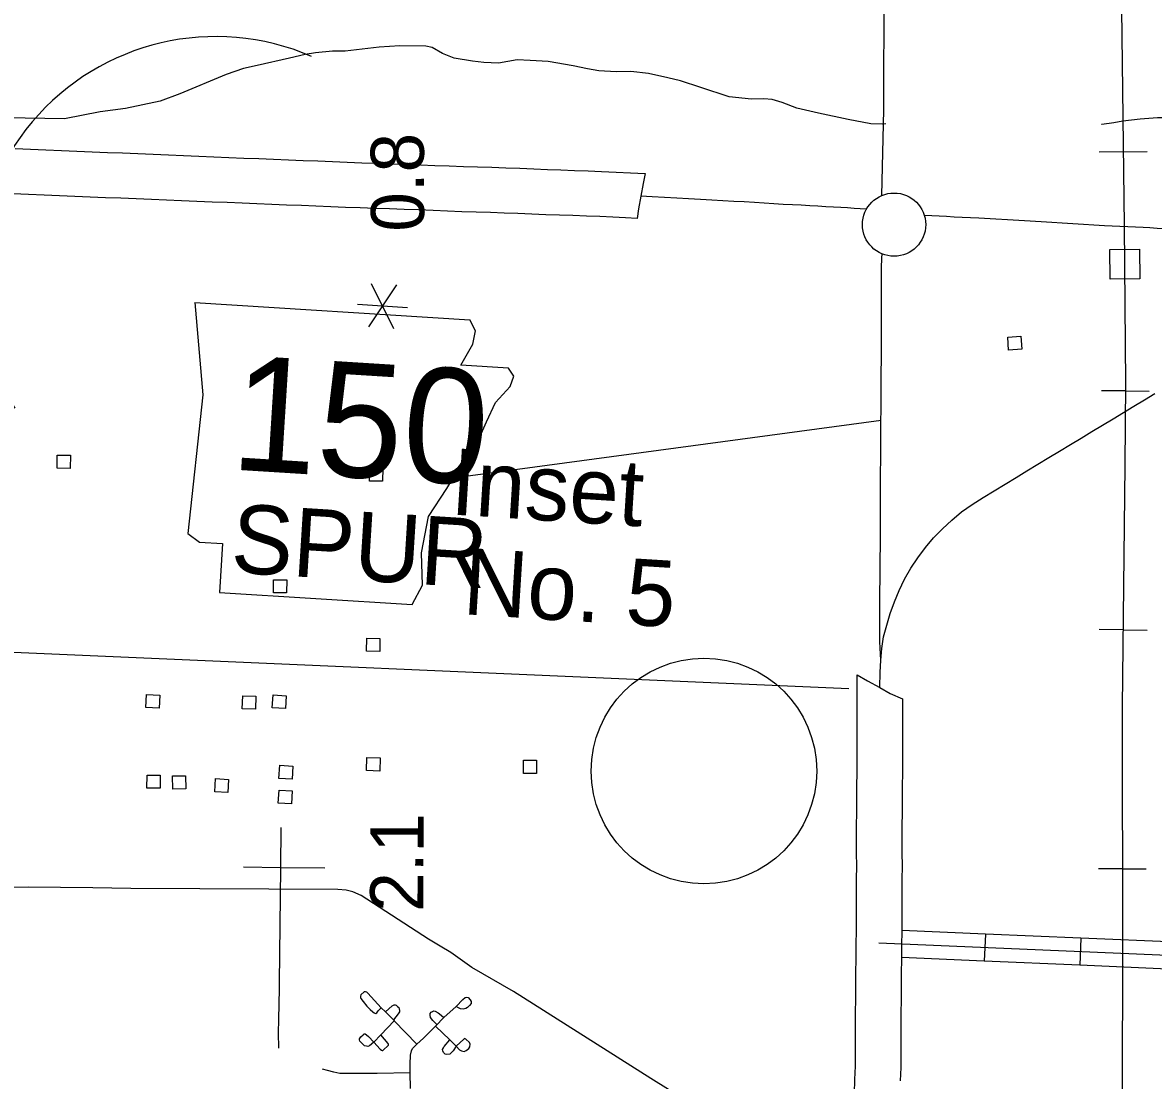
# Model space of a CAD drawing. Extents: x 1366406 to 1373462, y 376856 to 381998.
# Drawn here: x 1369108.1 to 1369209.2, y 380173.9 to 380268.5 of the extents above; entities that cross this region are included whole.
import ezdxf

# ---------------------------------------------------------------- set-up
doc = ezdxf.new("R2010")
doc.units = 0
for name, color, linetype in [('10', 7, 'Continuous'), ('15', 7, 'Continuous'), ('21', 7, 'Continuous'), ('24', 7, 'Continuous'), ('31', 7, 'Continuous'), ('32', 7, 'Continuous'), ('33', 7, 'Continuous'), ('35', 7, 'Continuous'), ('40', 7, 'Continuous'), ('43', 7, 'Continuous'), ('48', 7, 'Continuous'), ('5', 7, 'Continuous'), ('56', 7, 'Continuous'), ('63', 7, 'Continuous')]:
    doc.layers.add(name, color=color, linetype=linetype)

msp = doc.modelspace()

# ---------------------------------------------------------------- linework, layer by layer
at = {"layer": '10'}
for points in [[(1369107.42, 380257.24), (1369108.79, 380257.18), (1369110.16, 380257.12), (1369111.54, 380257.07), (1369112.92, 380257.01), (1369114.29, 380256.95), (1369115.66, 380256.89), (1369117.02, 380256.84), (1369118.38, 380256.79), (1369119.75, 380256.73), (1369121.12, 380256.68), (1369122.48, 380256.62), (1369123.84, 380256.56), (1369125.19, 380256.5), (1369126.53, 380256.44), (1369127.87, 380256.39), (1369129.2, 380256.34), (1369130.53, 380256.28), (1369131.85, 380256.23), (1369133.17, 380256.18), (1369134.49, 380256.13), (1369135.8, 380256.07), (1369137.11, 380256.02), (1369138.42, 380255.97), (1369139.73, 380255.93), (1369141.03, 380255.88), (1369142.35, 380255.84), (1369143.66, 380255.79), (1369144.95, 380255.73), (1369146.23, 380255.69), (1369147.51, 380255.64), (1369148.78, 380255.6), (1369150.05, 380255.57), (1369151.31, 380255.52), (1369152.57, 380255.47), (1369153.8, 380255.42), (1369155.02, 380255.37), (1369156.24, 380255.32), (1369157.45, 380255.28), (1369158.67, 380255.24), (1369159.87, 380255.19), (1369163.78, 380255.02), (1369163.59, 380254.12), (1369163.37, 380252.99), (1369163.16, 380251.85), (1369163.05, 380250.98)], [(1369163.05, 380250.98), (1369162.02, 380251.04), (1369160.87, 380251.09), (1369159.7, 380251.15), (1369158.51, 380251.19), (1369157.31, 380251.24), (1369156.1, 380251.28), (1369154.87, 380251.32), (1369153.64, 380251.37), (1369152.39, 380251.42), (1369151.16, 380251.47), (1369149.92, 380251.52), (1369148.66, 380251.55), (1369147.38, 380251.59), (1369146.09, 380251.64), (1369144.79, 380251.69), (1369143.49, 380251.74), (1369142.2, 380251.79), (1369140.9, 380251.83), (1369139.59, 380251.88), (1369138.27, 380251.92), (1369136.96, 380251.97), (1369135.64, 380252.03), (1369134.32, 380252.08), (1369133.01, 380252.13), (1369131.69, 380252.18), (1369130.36, 380252.24), (1369129.04, 380252.29), (1369127.71, 380252.34), (1369126.37, 380252.4), (1369125.02, 380252.45), (1369123.66, 380252.51), (1369122.3, 380252.57), (1369120.94, 380252.63), (1369119.59, 380252.69), (1369118.23, 380252.74), (1369116.86, 380252.79), (1369115.49, 380252.84), (1369114.11, 380252.9), (1369112.74, 380252.96), (1369111.37, 380253.02), (1369110, 380253.08), (1369108.61, 380253.13), (1369107.22, 380253.2)], [(1369183.57, 380251.82), (1369183.01, 380251.85), (1369182.46, 380251.88), (1369181.88, 380251.92), (1369181.27, 380251.95), (1369180.62, 380251.99), (1369179.94, 380252.03), (1369179.23, 380252.08), (1369178.5, 380252.12), (1369177.73, 380252.16), (1369176.94, 380252.2), (1369176.13, 380252.24), (1369175.29, 380252.29), (1369174.42, 380252.35), (1369173.54, 380252.41), (1369172.63, 380252.46), (1369171.69, 380252.51), (1369170.73, 380252.56), (1369169.73, 380252.63), (1369168.71, 380252.69), (1369167.66, 380252.75), (1369166.6, 380252.81), (1369165.51, 380252.86), (1369164.4, 380252.93), (1369163.37, 380252.99)], [(1369188.75, 380251.27), (1369189.43, 380251.25), (1369190.07, 380251.22), (1369190.74, 380251.18), (1369191.42, 380251.14), (1369192.13, 380251.11), (1369192.87, 380251.07), (1369193.63, 380251.03), (1369197.7, 380250.8), (1369199.21, 380250.7), (1369204.87, 380250.36)], [(1369204.87, 380250.36), (1369208.32, 380250.19), (1369208.92, 380250.16), (1369209.59, 380250.12), (1369210.32, 380250.08), (1369211.11, 380250.03), (1369211.95, 380249.97), (1369212.84, 380249.92), (1369213.76, 380249.87), (1369214.71, 380249.82), (1369215.69, 380249.76), (1369216.69, 380249.7), (1369217.71, 380249.63), (1369218.74, 380249.57), (1369219.74, 380249.5), (1369220.72, 380249.44), (1369221.66, 380249.38), (1369222.55, 380249.33), (1369223.36, 380249.28), (1369224.08, 380249.24), (1369224.69, 380249.23)], [(1369184.85, 380211.44), (1369184.82, 380212.04), (1369184.8, 380212.54), (1369184.78, 380213.12), (1369184.78, 380213.76), (1369184.78, 380214.45), (1369184.78, 380215.19), (1369184.77, 380215.98), (1369184.77, 380216.81), (1369184.78, 380217.7), (1369184.79, 380218.62), (1369184.79, 380219.59), (1369184.8, 380220.6), (1369184.81, 380221.63), (1369184.81, 380222.69), (1369184.81, 380223.77), (1369184.81, 380224.88), (1369184.81, 380225.99), (1369184.82, 380227.12), (1369184.83, 380228.26), (1369184.84, 380229.39), (1369184.85, 380230.53), (1369184.85, 380231.66), (1369184.86, 380232.79), (1369184.87, 380233.91), (1369184.88, 380235.03), (1369184.89, 380236.13), (1369184.89, 380237.23), (1369184.9, 380238.33), (1369184.91, 380239.42), (1369184.91, 380240.5), (1369184.91, 380241.58), (1369184.91, 380242.63), (1369184.91, 380243.66), (1369184.91, 380244.66), (1369184.9, 380245.63), (1369184.91, 380246.57), (1369184.93, 380247.42), (1369184.96, 380247.81)]]:
    msp.add_lwpolyline(points, dxfattribs=at)
at = {"layer": '15'}
for points in [[(1369184.85, 380211.44), (1369184.94, 380212.5), (1369185.09, 380213.55), (1369185.4, 380214.6), (1369185.7, 380215.64), (1369186.07, 380216.68), (1369186.49, 380217.7), (1369186.98, 380218.71), (1369187.54, 380219.68), (1369188.16, 380220.62), (1369188.84, 380221.53), (1369189.57, 380222.4), (1369190.36, 380223.22), (1369191.2, 380224), (1369192.08, 380224.73), (1369193.02, 380225.4), (1369194, 380226.01), (1369194.99, 380226.6), (1369195.98, 380227.2), (1369196.96, 380227.8), (1369197.93, 380228.4), (1369198.9, 380228.99), (1369199.87, 380229.58), (1369200.85, 380230.16), (1369201.83, 380230.75), (1369202.79, 380231.33), (1369203.74, 380231.91), (1369204.68, 380232.5), (1369205.63, 380233.06), (1369206.57, 380233.63), (1369207.5, 380234.19), (1369208.44, 380234.76), (1369209.37, 380235.32)], [(1369184.76, 380209), (1369184.79, 380210.38), (1369184.85, 380211.44)], [(1369182.51, 380172.69), (1369182.53, 380173.93), (1369182.58, 380175.12), (1369182.59, 380176.29), (1369182.6, 380177.48), (1369182.6, 380178.69), (1369182.6, 380179.92), (1369182.62, 380181.11), (1369182.63, 380182.3), (1369182.63, 380183.5), (1369182.64, 380184.7), (1369182.65, 380186.16), (1369182.67, 380187.11), (1369182.68, 380188.29), (1369182.69, 380189.47), (1369182.69, 380190.67), (1369182.69, 380191.86), (1369182.7, 380193.04), (1369182.69, 380194.23), (1369182.69, 380195.44), (1369182.69, 380196.64), (1369182.7, 380197.84), (1369182.71, 380199.03), (1369182.72, 380200.21), (1369182.73, 380201.39), (1369182.73, 380202.55), (1369182.73, 380203.71), (1369182.75, 380210.14), (1369183.65, 380209.6), (1369184.76, 380209), (1369185.7, 380208.48), (1369186.79, 380208)], [(1369186.79, 380208), (1369186.78, 380203.71), (1369186.78, 380202.55), (1369186.78, 380201.37), (1369186.77, 380200.18), (1369186.76, 380198.99), (1369186.75, 380197.81), (1369186.74, 380196.62), (1369186.74, 380195.44), (1369186.74, 380194.25), (1369186.75, 380193.04), (1369186.74, 380191.84), (1369186.74, 380190.65), (1369186.74, 380189.46), (1369186.73, 380188.26), (1369186.72, 380187.05), (1369186.7, 380186.11), (1369186.69, 380184.68), (1369186.68, 380183.48), (1369186.68, 380182.28), (1369186.67, 380181.07), (1369186.65, 380179.88), (1369186.65, 380178.69), (1369186.65, 380177.47), (1369186.64, 380176.25), (1369186.63, 380175.01), (1369186.58, 380173.82)]]:
    msp.add_lwpolyline(points, dxfattribs=at)
at = {"layer": '21'}
for p, q in [((1369123.47, 380243.47), (1369124.19, 380235.19)), ((1369148.58, 380240.94), (1369148.07, 380241.92)), ((1369148.36, 380239.72), (1369148.58, 380240.94)), ((1369147.29, 380237.86), (1369148.36, 380239.72)), ((1369151.53, 380237.6), (1369147.29, 380237.86)), ((1369152.03, 380236.88), (1369151.53, 380237.6)), ((1369151.7, 380235.94), (1369152.03, 380236.88)), ((1369124.19, 380235.19), (1369122.86, 380222.78)), ((1369150.37, 380234.51), (1369151.7, 380235.94)), ((1369149.58, 380232.78), (1369150.37, 380234.51)), ((1369148.62, 380230.64), (1369149.58, 380232.78)), ((1369147.12, 380228.67), (1369148.62, 380230.64)), ((1369146.04, 380226.82), (1369147.12, 380228.67)), ((1369144.38, 380224.31), (1369146.04, 380226.82)), ((1369143.76, 380221.06), (1369144.38, 380224.31)), ((1369122.86, 380222.78), (1369123.91, 380222.03)), ((1369123.91, 380222.03), (1369125.96, 380221.9)), ((1369125.96, 380221.9), (1369125.69, 380217.52)), ((1369143.85, 380218.17), (1369143.76, 380221.06)), ((1369142.92, 380216.44), (1369143.85, 380218.17)), ((1369125.69, 380217.52), (1369142.92, 380216.44))]:
    msp.add_line(p, q, dxfattribs=at)
for points in [[(1369123.47, 380243.47), (1369148.07, 380241.92)], [(1369146.6, 380227.77), (1369184.87, 380232.92)]]:
    msp.add_lwpolyline(points, dxfattribs=at)
at = {"layer": '24'}
msp.add_circle((1369186.04, 380250.43), 2.83, dxfattribs=at)
at = {"layer": '31'}
msp.add_lwpolyline([(1369184.93, 380253.04), (1369185.11, 380260.71)], dxfattribs=at)
at = {"layer": '32'}
for p, q in [((1369194.21, 380186.95), (1369194.1, 380184.52)), ((1369202.75, 380186.59), (1369202.65, 380184.16))]:
    msp.add_line(p, q, dxfattribs=at)
for points in [[(1369185.11, 380260.71), (1369185.19, 380282.45)], [(1369194.21, 380186.95), (1369186.72, 380187.27)], [(1369202.75, 380186.59), (1369194.21, 380186.95)], [(1369211.3, 380186.22), (1369202.75, 380186.59)], [(1369228.34, 380184.35), (1369227.29, 380184.33), (1369184.68, 380186.14)], [(1369194.1, 380184.52), (1369186.69, 380184.84)], [(1369202.65, 380184.16), (1369194.1, 380184.52)], [(1369211.2, 380183.79), (1369202.65, 380184.16)]]:
    msp.add_lwpolyline(points, dxfattribs=at)
at = {"layer": '33'}
for points in [[(1369131.18, 380196.5), (1369131.14, 380192.89), (1369131.03, 380182.58), (1369131.04, 380182.35), (1369131.04, 380182.07), (1369130.96, 380179.3), (1369130.95, 380178.11), (1369130.96, 380176.73)], [(1369135.11, 380192.86), (1369131.16, 380192.87), (1369127.85, 380192.95)], [(1369140.16, 380180.34), (1369138.96, 380181.67), (1369138.86, 380181.75), (1369138.75, 380181.79), (1369138.63, 380181.78), (1369138.34, 380181.51), (1369138.29, 380181.38), (1369138.3, 380181.27), (1369138.34, 380181.18), (1369138.53, 380180.92), (1369138.88, 380180.51), (1369139.17, 380180.21), (1369139.4, 380179.99), (1369139.52, 380179.9), (1369139.58, 380179.86), (1369139.67, 380179.85), (1369139.75, 380179.91), (1369139.89, 380180.07), (1369140.16, 380180.34)], [(1369140.54, 380179.98), (1369141.15, 380180.52), (1369141.31, 380180.61), (1369141.41, 380180.61), (1369141.49, 380180.58), (1369141.61, 380180.48), (1369141.73, 380180.37), (1369141.77, 380180.26), (1369141.79, 380180.12), (1369141.78, 380179.99), (1369141.68, 380179.81), (1369141.25, 380179.27)], [(1369142.77, 380173.14), (1369142.76, 380174.53), (1369142.74, 380175.3), (1369142.78, 380176.11), (1369142.87, 380176.5), (1369142.97, 380176.7), (1369143.35, 380177.09), (1369143.94, 380177.63), (1369145.02, 380178.71), (1369145.04, 380178.73), (1369145.77, 380179.49), (1369146.85, 380180.48), (1369146.85, 380180.48)], [(1369146.85, 380180.48), (1369147.45, 380181.1), (1369147.66, 380181.28), (1369147.8, 380181.31), (1369147.93, 380181.26), (1369148.11, 380181.07), (1369148.21, 380180.91), (1369148.2, 380180.75), (1369148.05, 380180.55), (1369147.88, 380180.39), (1369147.74, 380180.29), (1369147.5, 380180.22), (1369147.26, 380180.26), (1369147.07, 380180.36), (1369146.85, 380180.48)], [(1369140.16, 380180.34), (1369140.54, 380179.98), (1369141.25, 380179.27), (1369141.32, 380179.19), (1369143.35, 380177.09)], [(1369145.15, 380178.84), (1369144.77, 380179.23), (1369144.57, 380179.48), (1369144.54, 380179.69), (1369144.55, 380179.84), (1369144.64, 380179.96), (1369144.75, 380180.02), (1369144.84, 380180.07), (1369144.97, 380180.06), (1369145.25, 380179.89), (1369145.53, 380179.68), (1369145.77, 380179.49)], [(1369141.32, 380179.19), (1369140.11, 380177.93), (1369139.49, 380177.29), (1369139.12, 380176.96), (1369138.96, 380176.9), (1369138.83, 380176.91), (1369138.65, 380176.96), (1369138.25, 380177.37), (1369138.2, 380177.48), (1369138.21, 380177.58), (1369138.32, 380177.76), (1369138.53, 380177.94), (1369138.63, 380178.01), (1369138.71, 380178.01), (1369138.84, 380177.93), (1369139.03, 380177.78), (1369139.49, 380177.29)], [(1369145.02, 380178.71), (1369146.29, 380177.48), (1369146.85, 380176.91)], [(1369139.49, 380177.29), (1369140.06, 380176.65), (1369140.19, 380176.55), (1369140.25, 380176.54), (1369140.3, 380176.54), (1369140.8, 380177.02), (1369140.81, 380177.06), (1369140.78, 380177.15), (1369140.11, 380177.93)], [(1369146.85, 380176.91), (1369146.58, 380176.51), (1369146.29, 380176.2), (1369146.04, 380176.18), (1369145.89, 380176.21), (1369145.73, 380176.36), (1369145.67, 380176.5), (1369145.65, 380176.63), (1369145.72, 380176.76), (1369145.79, 380176.89), (1369146.29, 380177.48)], [(1369146.85, 380176.91), (1369147.16, 380176.6), (1369147.33, 380176.49), (1369147.57, 380176.45), (1369147.76, 380176.53), (1369147.99, 380176.71), (1369148.08, 380176.87), (1369148.11, 380177.1), (1369148.04, 380177.24), (1369147.72, 380177.56), (1369147.62, 380177.6), (1369147.54, 380177.55), (1369146.85, 380176.91)], [(1369142.76, 380174.53), (1369139.79, 380174.47), (1369137.12, 380174.46), (1369136.46, 380174.46), (1369135.91, 380174.58), (1369135.34, 380174.73), (1369134.91, 380174.86)]]:
    msp.add_lwpolyline(points, dxfattribs=at)
at = {"layer": '35'}
for points in [[(1369120.37, 380261.48), (1369117.29, 380260.83), (1369115, 380260.53), (1369111.83, 380259.89), (1369106.55, 380259.98), (1369097.06, 380260.2), (1369087.91, 380261.63), (1369085.17, 380262.04), (1369081.99, 380263.08), (1369078.68, 380264.7), (1369077.51, 380265.4), (1369076.42, 380266.1), (1369075.48, 380266.6), (1369074.11, 380267.1), (1369072.37, 380267.62), (1369070.66, 380267.97), (1369068.68, 380268.28), (1369066.69, 380268.81), (1369065.61, 380269.32), (1369064.11, 380269.97), (1369063.92, 380270.04)], [(1369185.31, 380259.46), (1369184.98, 380259.42), (1369183.95, 380259.46), (1369181.92, 380259.83), (1369179.27, 380260.39), (1369177.35, 380260.86), (1369176.04, 380261.37), (1369175.14, 380261.63), (1369174.4, 380261.68), (1369173.27, 380261.65), (1369171.3, 380261.88), (1369168.74, 380262.71), (1369166.92, 380263.29), (1369165.81, 380263.58), (1369164.06, 380263.96), (1369162.48, 380264.13), (1369161.17, 380264.11), (1369159.63, 380264.2), (1369158.61, 380264.37), (1369157.32, 380264.63), (1369155.08, 380265.02), (1369153.47, 380265.12), (1369152.33, 380265.19), (1369150.65, 380264.87), (1369149.35, 380264.95), (1369148.31, 380265.05), (1369146.69, 380265.33), (1369145.65, 380265.75), (1369144.7, 380266.27), (1369144.15, 380266.41), (1369141.82, 380266.42), (1369139.97, 380266.32), (1369136.93, 380265.94), (1369135.8, 380265.94), (1369134.27, 380265.79), (1369133.34, 380265.64), (1369131.94, 380265.34), (1369129.05, 380264.67), (1369127.83, 380264.4), (1369126.28, 380263.86), (1369122.14, 380262.13), (1369120.37, 380261.48)], [(1369214.29, 380260.1), (1369211.37, 380259.99), (1369209.62, 380260), (1369208.07, 380259.87), (1369206.52, 380259.69), (1369205.7, 380259.54), (1369204.63, 380259.39), (1369204.6, 380259.38)]]:
    msp.add_lwpolyline(points, dxfattribs=at)
at = {"layer": '40'}
for p, q in [((1369206.54, 380256.93), (1369204.4, 380256.91)), ((1369206.54, 380256.93), (1369208.68, 380256.96)), ((1369206.74, 380235.55), (1369204.6, 380235.57)), ((1369206.74, 380235.55), (1369208.87, 380235.53)), ((1369206.53, 380214.17), (1369204.39, 380214.19)), ((1369206.53, 380214.17), (1369208.67, 380214.15)), ((1369206.47, 380192.78), (1369204.33, 380192.78)), ((1369206.47, 380192.78), (1369208.6, 380192.78))]:
    msp.add_line(p, q, dxfattribs=at)
msp.add_lwpolyline([(1369206.39, 380269.7), (1369206.62, 380250.35), (1369206.74, 380236.22), (1369206.67, 380228.87), (1369206.46, 380207.29), (1369206.47, 380185.18), (1369206.46, 380173.22), (1369206.41, 380164.14), (1369206.46, 380145.13), (1369206.27, 380121.25), (1369205.35, 380086.27), (1369204.3, 380053.32), (1369204.17, 380048.19), (1369203.99, 380035.64)], dxfattribs=at)
msp.add_lwpolyline([(1369208.02, 380245.59), (1369205.38, 380245.56), (1369205.35, 380248.2), (1369207.99, 380248.23)], close=True, dxfattribs=at)
at = {"layer": '43'}
msp.add_lwpolyline([(1369171.32, 380169.64), (1369164.27, 380174.04), (1369151.99, 380181.8), (1369148.27, 380183.95), (1369146.39, 380185.29), (1369145.44, 380185.87), (1369144.38, 380186.48), (1369138.36, 380190.4), (1369137.63, 380190.73), (1369137.03, 380190.87), (1369136.27, 380190.94), (1369117.77, 380191.02), (1369114.37, 380191.09), (1369108.58, 380191.16), (1369069.61, 380190.92), (1369058.09, 380190.94), (1369055.07, 380190.89), (1369037.81, 380190.85), (1369033.17, 380190.78), (1369022.27, 380190.76)], dxfattribs=at)
at = {"layer": '48'}
for p, q in [((1369139.26, 380245.17), (1369141.26, 380241.14)), ((1369141.51, 380245.03), (1369139.02, 380241.28)), ((1369138.02, 380243.3), (1369142.51, 380243.01))]:
    msp.add_line(p, q, dxfattribs=at)
at = {"layer": '5'}
msp.add_lwpolyline([(1369181.98, 380208.88), (1369098.32, 380212.54)], dxfattribs=at)
at = {"layer": '56'}
for points in [[(1369196.29, 380239.2), (1369196.21, 380240.37), (1369197.38, 380240.45), (1369197.46, 380239.29)], [(1369111.16, 380228.64), (1369111.18, 380229.81), (1369112.36, 380229.79), (1369112.33, 380228.62)], [(1369139.1, 380227.49), (1369139.11, 380228.66), (1369140.29, 380228.64), (1369140.27, 380227.47)], [(1369130.51, 380217.49), (1369130.52, 380218.66), (1369131.7, 380218.65), (1369131.69, 380217.48)], [(1369138.85, 380212.25), (1369138.86, 380213.42), (1369140.04, 380213.41), (1369140.02, 380212.24)], [(1369119.11, 380207.21), (1369119.16, 380208.38), (1369120.34, 380208.32), (1369120.28, 380207.15)], [(1369127.73, 380207.09), (1369127.77, 380208.26), (1369128.94, 380208.23), (1369128.9, 380207.06)], [(1369130.41, 380207.19), (1369130.49, 380208.36), (1369131.66, 380208.28), (1369131.58, 380207.12)], [(1369138.85, 380201.58), (1369138.88, 380202.75), (1369140.06, 380202.71), (1369140.02, 380201.54)], [(1369131.01, 380200.88), (1369131.08, 380202.05), (1369132.25, 380201.98), (1369132.18, 380200.81)], [(1369152.88, 380201.33), (1369152.89, 380202.51), (1369154.06, 380202.5), (1369154.05, 380201.32)], [(1369119.2, 380200.01), (1369119.21, 380201.18), (1369120.38, 380201.17), (1369120.37, 380200)], [(1369121.5, 380199.92), (1369121.48, 380201.1), (1369122.65, 380201.12), (1369122.67, 380199.95)], [(1369125.26, 380199.69), (1369125.33, 380200.86), (1369126.5, 380200.78), (1369126.43, 380199.61)], [(1369130.95, 380198.67), (1369131.02, 380199.84), (1369132.19, 380199.77), (1369132.12, 380198.6)]]:
    msp.add_lwpolyline(points, close=True, dxfattribs=at)
at = {"layer": '63'}
msp.add_circle((1369169.03, 380201.54), 10.09, dxfattribs=at)
msp.add_arc((1369125.36, 380245.77), 21.49, 66.5152, 213.1778, dxfattribs=at)

# ---------------------------------------------------------------- texts
at = {"layer": '21'}
for s, height, p in [('150', 10.264, (1369126.58, 380228.53)), ('SPUR', 6.159, (1369126.62, 380219.32))]:
    msp.add_text(s, height=height, rotation=356.4139, dxfattribs=at).set_placement(p)
at = {"layer": '48'}
for s, rotation, p in [('0.8', 90.2255, (1369144, 380249.81)), ('2.1', 89.7016, (1369143.91, 380188.94))]:
    msp.add_text(s, height=4.752, rotation=rotation, dxfattribs=at).set_placement(p)
at = {"layer": '63'}
for s, p in [('Inset', (1369146.27, 380224.5)), ('No. 5', (1369147.37, 380215.58))]:
    msp.add_text(s, height=5.94, rotation=356.4139, dxfattribs=at).set_placement(p)

doc.saveas('drawing.dxf')
